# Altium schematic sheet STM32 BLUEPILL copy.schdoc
size 342 x 240 mm
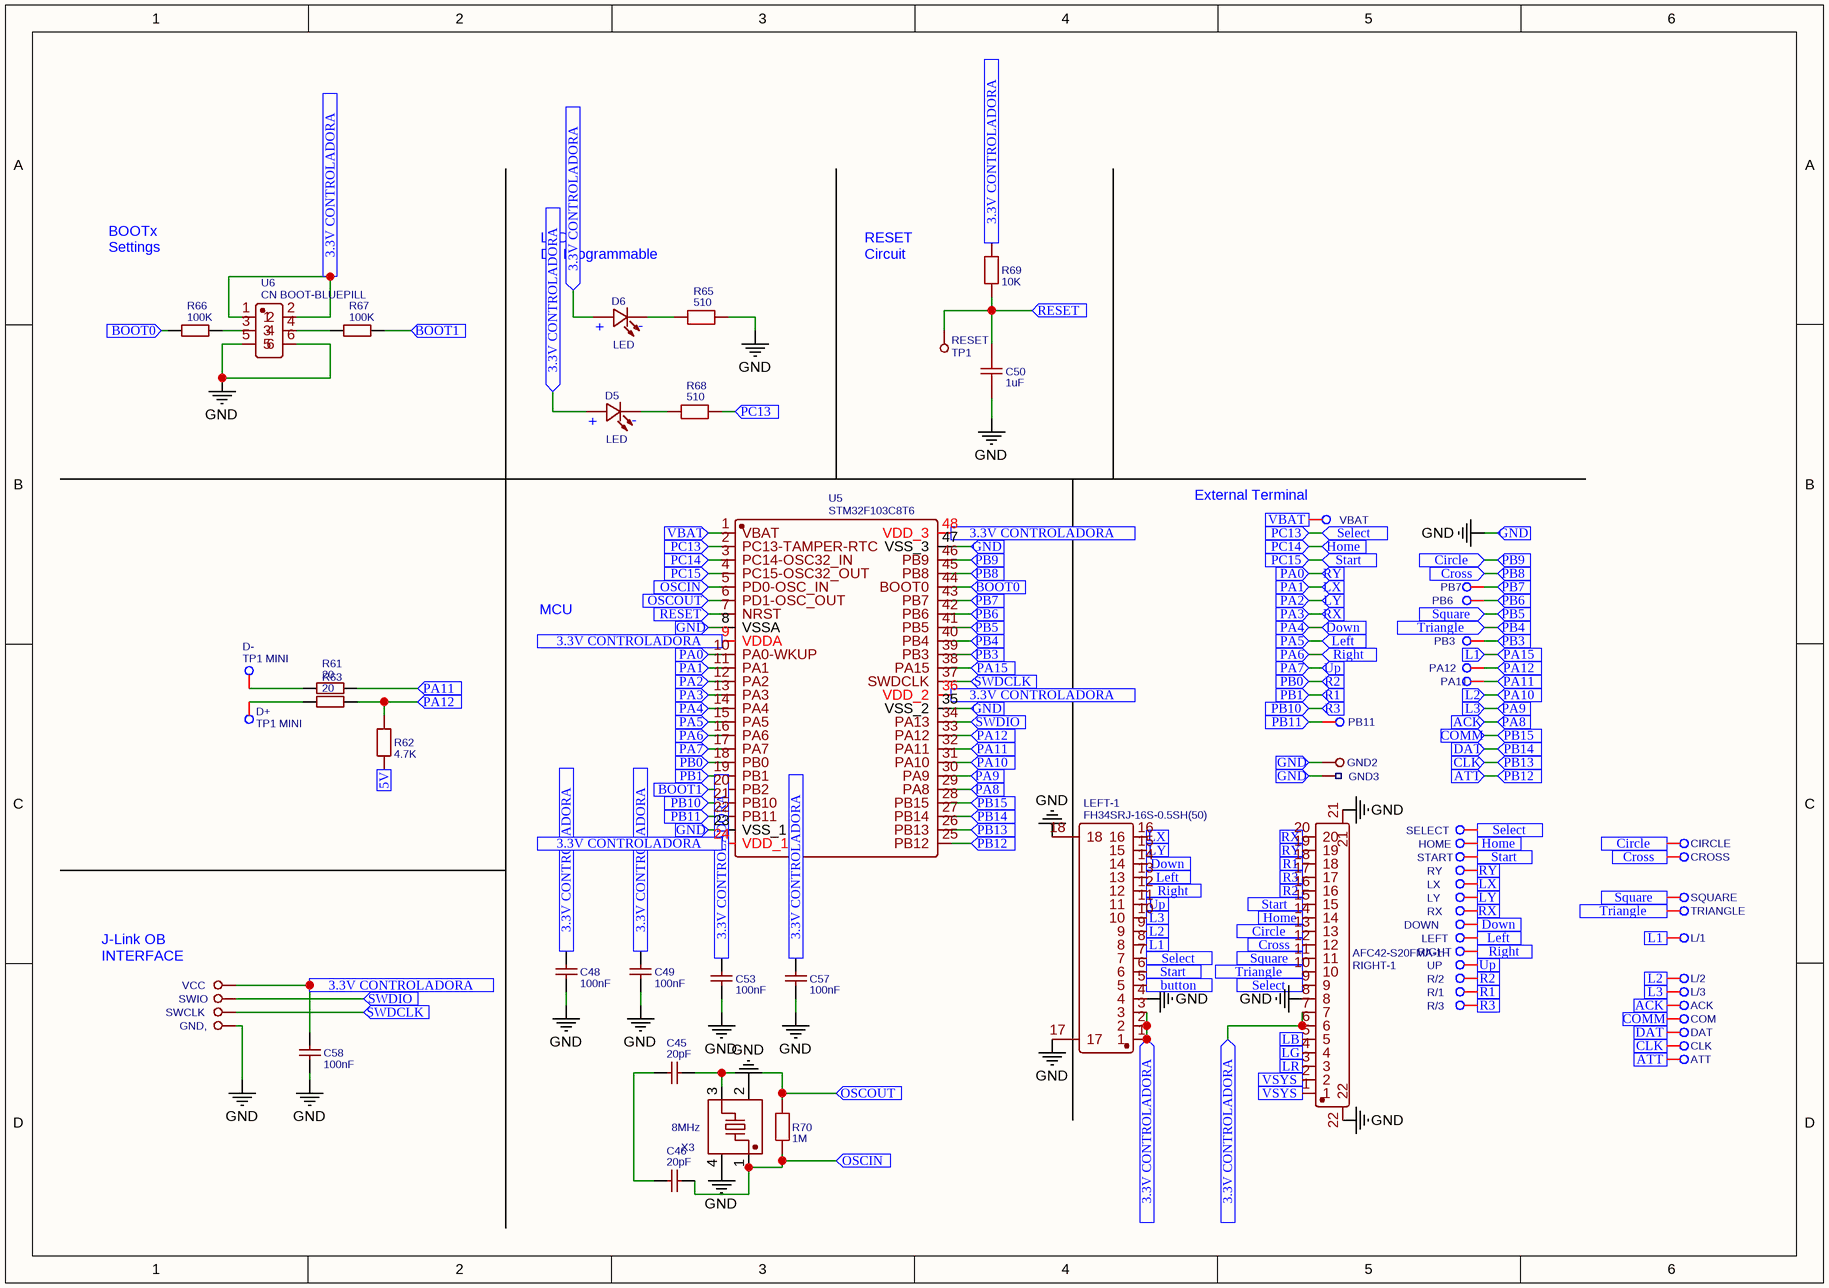
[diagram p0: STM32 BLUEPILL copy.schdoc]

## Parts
ACK  TP1 MINI  [TP1 MINI]  (value not drawn)
ATT  TP1 MINI  [TP1 MINI]  (value not drawn)
C45  20pF  [C0402]
C46  20pF  [C0402]
C48  100nF  [C0402]
C49  100nF  [C0402]
C50  1uF  [C0402]
C53  100nF  [C0402]
C57  100nF  [C0402]
C58  100nF  [C0402]
CIRCLE  TP1 MINI  [TP1 MINI]  (value not drawn)
CLK  TP1 MINI  [TP1 MINI]  (value not drawn)
COM  TP1 MINI  [TP1 MINI]  (value not drawn)
CROSS  TP1 MINI  [TP1 MINI]  (value not drawn)
D5  LED  [LED-SMD_L2.0-W0.5-RD]
D6  LED  [LED-SMD_L2.0-W0.5-RD]
D+  TP1 MINI  [TP1 MINI]
D-  TP1 MINI  [TP1 MINI]
DAT  TP1 MINI  [TP1 MINI]  (value not drawn)
DOWN  TP1 MINI  [TP1 MINI]  (value not drawn)
GND2  TP1  [TP1]  (value not drawn)
GND3  TP2  [TP2]  (value not drawn)
GND,  TP1  [TP1]  (value not drawn)
HOME  TP1 MINI  [TP1 MINI]  (value not drawn)
L/1  TP1 MINI  [TP1 MINI]  (value not drawn)
L/2  TP1 MINI  [TP1 MINI]  (value not drawn)
L/3  TP1 MINI  [TP1 MINI]  (value not drawn)
LEFT  TP1 MINI  [TP1 MINI]  (value not drawn)
LEFT-1  FH34SRJ-16S-0.5SH(50)  [FFC-SMD_16P-P0.50_FH34SRJ-16S-0.5SH]
LX  TP1 MINI  [TP1 MINI]  (value not drawn)
LY  TP1 MINI  [TP1 MINI]  (value not drawn)
PA11  TP1 MINI  [TP1 MINI]  (value not drawn)
PA12  TP1 MINI  [TP1 MINI]  (value not drawn)
PB3  TP1 MINI  [TP1 MINI]  (value not drawn)
PB6  TP1 MINI  [TP1 MINI]  (value not drawn)
PB7  TP1 MINI  [TP1 MINI]  (value not drawn)
PB11  TP1 MINI  [TP1 MINI]  (value not drawn)
R61  20  [R0402]
R62  4.7K  [R0402]
R63  20  [R0402]
R65  510  [R0402]
R66  100K  [R0402]
R67  100K  [R0402]
R68  510  [R0402]
R69  10K  [R0402]
R70  1M  [R0402]
R/1  TP1 MINI  [TP1 MINI]  (value not drawn)
R/2  TP1 MINI  [TP1 MINI]  (value not drawn)
R/3  TP1 MINI  [TP1 MINI]  (value not drawn)
RESET  TP1  [TP1]
RIGHT  TP1 MINI  [TP1 MINI]  (value not drawn)
RIGHT-1  AFC42-S20FMA-1H  [FFC-SMD_20P-P0.50_AFC42-S20FMA-1H]
RX  TP1 MINI  [TP1 MINI]  (value not drawn)
RY  TP1 MINI  [TP1 MINI]  (value not drawn)
SELECT  TP1 MINI  [TP1 MINI]  (value not drawn)
SQUARE  TP1 MINI  [TP1 MINI]  (value not drawn)
START  TP1 MINI  [TP1 MINI]  (value not drawn)
SWCLK  TP1  [TP1]  (value not drawn)
SWIO  TP1  [TP1]  (value not drawn)
TRIANGLE  TP1 MINI  [TP1 MINI]  (value not drawn)
U5  STM32F103C8T6  [LQFP-48_L7.0-W7.0-P0.50-LS9.0-BL]
U6  CN BOOT-BLUEPILL  [BOOT-BLUEPILL]
UP  TP1 MINI  [TP1 MINI]  (value not drawn)
VBAT  TP1 MINI  [TP1 MINI]  (value not drawn)
VCC  TP1  [TP1]  (value not drawn)
X3  8MHz  [OSC-SMD_4P-L3.2-W2.5-BL]

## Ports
3.3V CONTROLADORA (in), 5V (in), ACK (in), ATT (in), BOOT0 (in), BOOT1 (in), button (in), Circle (in), CLK (in), COMM (in), Cross (in), DAT (in), Down (in), GND (in), Home (in), L1 (in), L2 (in), L3 (in), LB (in), Left (in), LG (in), LR (in), LX (in), LY (in), OSCIN (in), OSCOUT (in), PA0 (in), PA1 (in), PA2 (in), PA3 (in), PA4 (in), PA5 (in), PA6 (in), PA7 (in), PA8 (in), PA9 (in), PA10 (in), PA11 (in), PA12 (in), PA15 (in), PB0 (in), PB1 (in), PB3 (in), PB4 (in), PB5 (in), PB6 (in), PB7 (in), PB8 (in), PB9 (in), PB10 (in), PB11 (in), PB12 (in), PB13 (in), PB14 (in), PB15 (in), PC13 (in), PC14 (in), PC15 (in), R1 (in), R2 (in), R3 (in), RESET (in), Right (in), RX (in), RY (in), Select (in), Square (in), Start (in), SWDCLK (in), SWDIO (in), Triangle (in), Up (in), VBAT (in), VSYS (in)

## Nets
GND: C48.1 C49.1 C50.1 C53.1 C57.1 C58.1 GND2.1 GND3.1 GND,.1 LEFT-1.4 LEFT-1.17 LEFT-1.18 R65.2 RIGHT-1.8 RIGHT-1.21 RIGHT-1.22 U5.8(VSSA) U5.23(VSS_1) U5.35(VSS_2) U5.47(VSS_3) U6.5 U6.6 X3.2(GND) X3.4(GND) ; port GND
3.3V CONTROLADORA: C48.2 C49.2 C53.2 C57.2 C58.2 D5.2 D6.2 LEFT-1.1 LEFT-1.2 LEFT-1.3 R69.2 RIGHT-1.6 RIGHT-1.7 U5.9(VDDA) U5.24(VDD_1) U5.36(VDD_2) U5.48(VDD_3) U6.1 U6.2 VCC.1 ; port 3.3V CONTROLADORA
5V: R62.1 ; port 5V
ACK: ACK.1 U5.29(PA8) ; port PA8, port ACK
ATT: ATT.1 U5.25(PB12) ; port PB12, port ATT
BOOT0: R66.1 U5.44(BOOT0) ; port BOOT0
BOOT1: R67.2 U5.20(PB2) ; port BOOT1
button: LEFT-1.5 ; port button
Circle: CIRCLE.1 RIGHT-1.13 U5.46(PB9) ; port PB9, port Circle
CLK: CLK.1 U5.26(PB13) ; port PB13, port CLK
COMM: COM.1 U5.28(PB15) ; port PB15, port COMM
Cross: CROSS.1 RIGHT-1.12 U5.45(PB8) ; port PB8, port Cross
DAT: DAT.1 U5.27(PB14) ; port PB14, port DAT
Down: DOWN.1 LEFT-1.14 U5.14(PA4) ; port PA4, port Down
Home: HOME.1 RIGHT-1.14 U5.3(PC14-OSC32_IN) ; port PC14, port Home
L1: L/1.1 LEFT-1.8 U5.38(PA15) ; port PA15, port L1
L2: L/2.1 LEFT-1.9 U5.31(PA10) ; port PA10, port L2
L3: L/3.1 LEFT-1.10 U5.30(PA9) ; port PA9, port L3
LB: RIGHT-1.5 ; port LB
Left: LEFT.1 LEFT-1.13 U5.15(PA5) ; port PA5, port Left
LG: RIGHT-1.4 ; port LG
LR: RIGHT-1.3 ; port LR
LX: LEFT-1.16 LX.1 U5.11(PA1) ; port PA1, port LX
LY: LEFT-1.15 LY.1 U5.12(PA2) ; port PA2, port LY
OSCIN: C46.2 R70.1 U5.5(PD0-OSC_IN) X3.1 ; port OSCIN
OSCOUT: C45.2 R70.2 U5.6(PD1-OSC_OUT) X3.3 ; port OSCOUT
PA0: RIGHT-1.19 RY.1 U5.10(PA0-WKUP) ; port PA0, port RY
PA3: RIGHT-1.20 RX.1 U5.13(PA3) ; port PA3, port RX
PA6: LEFT-1.12 RIGHT.1 U5.16(PA6) ; port PA6, port Right
PA7: LEFT-1.11 U5.17(PA7) UP.1 ; port PA7, port Up
PA11: PA11.1 R61.2 U5.32(PA11) ; port PA11
PA12: PA12.1 R62.2 R63.2 U5.33(PA12) ; port PA12
PB0: R/2.1 RIGHT-1.16 U5.18(PB0) ; port PB0, port R2
PB1: R/1.1 RIGHT-1.18 U5.19(PB1) ; port PB1, port R1
PB3: PB3.1 U5.39(PB3) ; port PB3
PB4: RIGHT-1.10 TRIANGLE.1 U5.40(PB4) ; port PB4, port Triangle
PB5: RIGHT-1.11 SQUARE.1 U5.41(PB5) ; port PB5, port Square
PB6: PB6.1 U5.42(PB6) ; port PB6
PB7: PB7.1 U5.43(PB7) ; port PB7
PB10: R/3.1 RIGHT-1.17 U5.21(PB10) ; port PB10, port R3
PB11: PB11.1 U5.22(PB11) ; port PB11
PC13: LEFT-1.7 R68.2 RIGHT-1.9 SELECT.1 U5.2(PC13-TAMPER-RTC) ; port PC13, port Select
PC15: LEFT-1.6 RIGHT-1.15 START.1 U5.4(PC15-OSC32_OUT) ; port PC15, port Start
RESET: C50.2 R69.1 RESET.1 U5.7(NRST) ; port RESET
SWDCLK: SWCLK.1 U5.37(SWDCLK) ; port SWDCLK
SWDIO: SWIO.1 U5.34(PA13) ; port SWDIO
VBAT: U5.1(VBAT) VBAT.1 ; port VBAT
VSYS: RIGHT-1.1 RIGHT-1.2 ; port VSYS
NetC45_1: C45.1 C46.1
NetD5_1: D5.1 R68.1
NetD6_1: D6.1 R65.1
NetD+_1: D+.1 R63.1
NetD-_1: D-.1 R61.1
NetR66_2: R66.2 U6.3
NetR67_1: R67.1 U6.4

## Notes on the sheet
- (near R66) BOOTx
  Settings
- (near D6) LED
  D2 Programmable
- RESET
  Circuit
- (near VBAT) External Terminal
- MCU
- J-Link OB
  INTERFACE

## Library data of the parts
ACK ATT CIRCLE CLK COM CROSS D+ D- DAT DOWN HOME L/1-L/3 LEFT LX LY PA11 PA12 PB3 PB6 PB7 PB11 R/1-R/3 RIGHT RX RY SELECT SQUARE START TRIANGLE UP VBAT = TP1 MINI: Contributor: Marlon Vinicius
C45 C46 = 20pF: Manufacturer: YAGEO; Manufacturer Part: CC0402JRNPO9BN200; nameAlias: Capacitance
C48 C49 C53 C57 C58 = 100nF: Manufacturer: YAGEO; Manufacturer Part: CC0402KRX7R8BB104; nameAlias: Capacitance; Contributor: LCSC
C50 = 1uF: Manufacturer: SAMSUNG; Manufacturer Part: CL05A105KA5NQNC; nameAlias: Capacitance
D5 D6 = LED: Manufacturer: TOGIALED; Manufacturer Part: TJ-S2005SW9TGLC0A-A5; Contributor: LCSC
GND2 GND, RESET SWCLK SWIO VCC = TP1: Contributor: Marlon Vinicius
GND3 = TP2: Contributor: Marlon Vinicius
LEFT-1 = FH34SRJ-16S-0.5SH(50): Manufacturer: Hirose; Contributor: LCSC
R61 R63 = 20: Manufacturer: YAGEO; Manufacturer Part: RC0402FR-0720RL; nameAlias: Resistance (Ohms)
R62 = 4.7K: Manufacturer: PANASONIC; Manufacturer Part: ERJPA2F4701X; nameAlias: Resistance (Ohms); Contributor: LCSC
R65 R68 = 510: Manufacturer: PANASONIC; Manufacturer Part: ERJ2RKF5100X; nameAlias: Resistance (Ohms); Contributor: LCSC
R66 R67 = 100K: Manufacturer: YAGEO; Manufacturer Part: RC0402FR-07100KL; nameAlias: Resistance (Ohms)
R69 = 10K: Manufacturer: PANASONIC; Manufacturer Part: ERJPA2F1002X; nameAlias: Resistance (Ohms); Contributor: LCSC
R70 = 1M: Manufacturer: PANASONIC; Manufacturer Part: ERJPA2J105X; nameAlias: Resistance (Ohms); Contributor: LCSC
RIGHT-1 = AFC42-S20FMA-1H: Manufacturer: JUSHUO; Contributor: LCSC
U5 = STM32F103C8T6: Manufacturer: STMicroelectronics; SMT Type: Basic
U6 = CN BOOT-BLUEPILL: Contributor: Marlon Vinicius
X3 = 8MHz: Manufacturer: Suzhou Liming Elec; Manufacturer Part: 3225-8.00-10-10-10/A; nameAlias: Frequency; Contributor: LCSC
